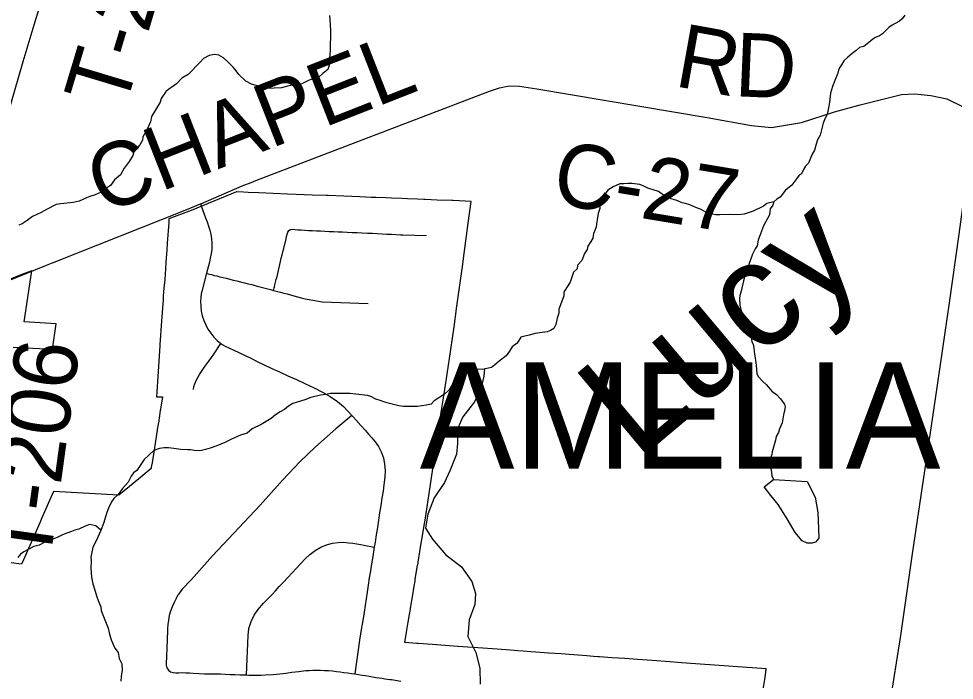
# Model space of a CAD drawing. Extents: x 0 to 34, y 0 to 22.
# Drawn here: x 8.3551 to 8.7724, y 14.1693 to 14.4643 of the extents above; entities that cross this region are included whole.
import ezdxf

# ---------------------------------------------------------------- set-up
doc = ezdxf.new("R2010")
doc.units = 0
for name, color, linetype in [('GM_X_City_Street', 7, 'Continuous'), ('GM_X_Corporation_Text', 7, 'Continuous'), ('GM_X_County_Road', 7, 'Continuous'), ('GM_X_County_Road_Text', 7, 'Continuous'), ('GM_X_Minor_Lake', 7, 'Continuous'), ('GM_X_Minor_River', 7, 'Continuous'), ('GM_X_Minor_River_Text', 7, 'Continuous'), ('GM_X_State_Route', 7, 'Continuous'), ('GM_X_Township_Road', 7, 'Continuous'), ('GM_X_Township_Road_Text', 7, 'Continuous')]:
    doc.layers.add(name, color=color, linetype=linetype)

msp = doc.modelspace()

# ---------------------------------------------------------------- linework, layer by layer
at = {"layer": 'GM_X_City_Street'}
for points in [[(8.6871, 14.16431), (8.68786, 14.16966), (8.68851, 14.17416), (8.68853, 14.17436), (8.67378, 14.17544), (8.65075, 14.17712), (8.6455, 14.1775), (8.63768, 14.17807), (8.63113, 14.17855), (8.62546, 14.17897), (8.61979, 14.17938), (8.61413, 14.17979), (8.61363, 14.17983), (8.61149, 14.17999), (8.60846, 14.18021), (8.60279, 14.18062), (8.60061, 14.18078), (8.59713, 14.18104), (8.59447, 14.18124), (8.59146, 14.18146), (8.58579, 14.18188), (8.58359, 14.18204), (8.58013, 14.1823), (8.57768, 14.18248), (8.57446, 14.18271), (8.56848, 14.18316), (8.56215, 14.18362), (8.55105, 14.18443), (8.54537, 14.18485), (8.5395, 14.18528), (8.53344, 14.18572), (8.53273, 14.18577), (8.52737, 14.18616), (8.52827, 14.19166), (8.52887, 14.19529), (8.52943, 14.19867), (8.52982, 14.20105), (8.52992, 14.20162), (8.52998, 14.20201), (8.53018, 14.20324), (8.53019, 14.20326), (8.53059, 14.20567), (8.53167, 14.21224), (8.53167, 14.21225), (8.53174, 14.21268), (8.5319, 14.21367), (8.53192, 14.21376), (8.53201, 14.21429), (8.53201, 14.21432), (8.5329, 14.21969), (8.53323, 14.22173), (8.53323, 14.22173), (8.53324, 14.22173), (8.53327, 14.22193), (8.53405, 14.22669), (8.53405, 14.2267), (8.53454, 14.22962), (8.53521, 14.2337), (8.53597, 14.23832), (8.53597, 14.23833), (8.53637, 14.24071), (8.53859, 14.25558), (8.54039, 14.26764), (8.54089, 14.27099), (8.54299, 14.28503), (8.54515, 14.29894), (8.54621, 14.30579), (8.54792, 14.31682), (8.54932, 14.32693), (8.55059, 14.33609), (8.55275, 14.35175), (8.55303, 14.35385), (8.55382, 14.35961), (8.55567, 14.3731), (8.557, 14.38285), (8.54884, 14.38318), (8.5483, 14.3832), (8.54176, 14.38346), (8.53637, 14.38367), (8.53585, 14.38369), (8.53299, 14.38381), (8.52856, 14.38399), (8.52608, 14.38408), (8.52146, 14.38427), (8.51901, 14.38437), (8.51437, 14.38455), (8.51235, 14.38463), (8.50727, 14.38484), (8.50017, 14.38512), (8.49308, 14.3854), (8.49244, 14.38543), (8.48598, 14.38569), (8.48597, 14.38569), (8.47888, 14.38597), (8.47505, 14.38612), (8.46221, 14.38663), (8.45751, 14.38685), (8.45534, 14.38694), (8.4524, 14.38706), (8.45227, 14.38706), (8.43204, 14.37875), (8.42214, 14.3751), (8.42203, 14.37337), (8.42141, 14.36427), (8.4212, 14.36125), (8.42081, 14.35554), (8.42045, 14.35017), (8.42027, 14.3482), (8.42025, 14.34788), (8.41992, 14.34408), (8.41962, 14.34069), (8.41962, 14.34069), (8.41951, 14.33899), (8.41887, 14.32955), (8.41814, 14.31883), (8.41811, 14.31844), (8.41733, 14.30693), (8.41657, 14.29575), (8.41926, 14.29568), (8.41925, 14.29562), (8.41854, 14.2912), (8.41836, 14.29002), (8.41828, 14.28955), (8.41794, 14.28741), (8.41787, 14.28691), (8.4178, 14.28649), (8.41757, 14.28507), (8.41755, 14.28492), (8.41732, 14.28348), (8.41694, 14.28111), (8.41692, 14.28095), (8.41691, 14.28086), (8.41565, 14.27298), (8.41459, 14.26627), (8.41446, 14.26546), (8.41442, 14.26522), (8.41425, 14.26415), (8.41425, 14.2641), (8.41418, 14.26369), (8.40864, 14.25916), (8.40448, 14.25575), (8.39972, 14.25186), (8.3707, 14.25346), (8.3655, 14.24169), (8.36452, 14.23947), (8.35728, 14.22306), (8.35642, 14.22112), (8.31928, 14.22581)], [(8.35258, 14.31787), (8.37017, 14.31688), (8.37183, 14.32829), (8.35759, 14.32908), (8.36092, 14.35195), (8.35773, 14.35068), (8.35649, 14.35018), (8.34984, 14.34754)]]:
    msp.add_lwpolyline(points, dxfattribs=at)
at = {"layer": 'GM_X_County_Road'}
msp.add_lwpolyline([(8.33552, 14.34148), (8.36753, 14.35434), (8.36982, 14.35526), (8.37092, 14.35571), (8.42938, 14.37892), (8.43623, 14.38173), (8.43641, 14.3818), (8.45481, 14.38982), (8.45875, 14.39129), (8.46094, 14.39211), (8.56512, 14.43194), (8.56952, 14.43353), (8.5739, 14.43436), (8.57844, 14.43425), (8.58618, 14.43309), (8.66213, 14.42022), (8.68193, 14.41665), (8.69085, 14.41576), (8.7042, 14.41804), (8.71903, 14.42272), (8.73045, 14.42593), (8.74887, 14.43053), (8.75475, 14.43076), (8.76193, 14.43), (8.76915, 14.4286), (8.77664, 14.42485)], dxfattribs=at)
at = {"layer": 'GM_X_Minor_Lake'}
msp.add_line((8.68761, 14.25555), (8.69175, 14.25887), dxfattribs=at)
msp.add_lwpolyline([(8.69175, 14.25887), (8.70685, 14.25788), (8.71035, 14.25098), (8.71156, 14.24411), (8.71182, 14.23689), (8.71194, 14.2327), (8.71057, 14.23083), (8.70905, 14.23047), (8.70677, 14.23051), (8.7045, 14.2315), (8.70152, 14.23516), (8.69782, 14.24131), (8.69394, 14.24765), (8.69059, 14.2517), (8.68761, 14.25555)], dxfattribs=at)
at = {"layer": 'GM_X_Minor_River'}
for points in [[(8.49374, 14.46566), (8.49406, 14.46185), (8.4942, 14.4588), (8.49405, 14.45025), (8.49383, 14.44816), (8.49359, 14.44531), (8.49356, 14.4436), (8.49296, 14.44171), (8.49084, 14.43984), (8.48929, 14.43854), (8.4847, 14.43691), (8.48145, 14.43525), (8.47916, 14.43491), (8.47554, 14.43441), (8.47229, 14.43351), (8.46582, 14.43325), (8.46109, 14.43447), (8.45901, 14.43508), (8.45637, 14.43646), (8.45338, 14.43936), (8.45208, 14.4411), (8.45077, 14.44264), (8.44853, 14.44496), (8.44648, 14.4469), (8.4444, 14.44808), (8.44251, 14.4483), (8.44003, 14.44796), (8.43753, 14.44649), (8.43599, 14.44499), (8.43076, 14.43938), (8.42788, 14.43772), (8.42556, 14.43529), (8.42094, 14.43194), (8.41861, 14.42875), (8.4182, 14.42705), (8.41644, 14.42404), (8.41429, 14.42065), (8.41387, 14.41838), (8.41248, 14.41498), (8.41052, 14.41159), (8.41031, 14.41007), (8.40913, 14.408), (8.40642, 14.405), (8.40601, 14.4033), (8.40445, 14.40066), (8.40212, 14.39766), (8.40054, 14.39465)], [(8.75036, 14.4659), (8.74919, 14.4642), (8.74804, 14.46327), (8.74612, 14.46217), (8.74477, 14.46143), (8.74324, 14.46032), (8.74034, 14.45751), (8.73899, 14.45659), (8.73727, 14.45586), (8.73611, 14.45512), (8.73438, 14.45363), (8.73207, 14.45195), (8.73016, 14.45142), (8.72862, 14.45011), (8.72688, 14.44881), (8.72496, 14.44713), (8.72322, 14.44545), (8.72205, 14.44376), (8.72088, 14.44188), (8.72046, 14.43999), (8.71908, 14.43678), (8.71808, 14.43413), (8.71727, 14.43111), (8.71682, 14.42712), (8.71641, 14.42523), (8.71578, 14.42162), (8.7148, 14.41993), (8.714, 14.41766), (8.71258, 14.41236), (8.71141, 14.41029), (8.71081, 14.4084), (8.71, 14.40575), (8.70902, 14.40387), (8.70803, 14.40141), (8.70743, 14.3999), (8.70608, 14.39859), (8.70511, 14.39709), (8.70431, 14.3952), (8.70316, 14.39446)], [(8.40054, 14.39465), (8.39785, 14.39241), (8.39609, 14.38997), (8.39379, 14.38849), (8.39186, 14.387), (8.38918, 14.38572), (8.38689, 14.385), (8.38536, 14.38445), (8.3821, 14.38299), (8.37943, 14.38228), (8.37391, 14.3818), (8.37181, 14.38146), (8.36759, 14.37925), (8.3651, 14.37796), (8.36127, 14.37613), (8.35895, 14.37427), (8.35665, 14.37279), (8.35512, 14.37224)], [(8.70316, 14.39446), (8.70199, 14.39296), (8.69985, 14.38995), (8.69716, 14.38791), (8.69482, 14.38472), (8.69329, 14.38379), (8.69194, 14.38268), (8.69153, 14.38116), (8.69036, 14.37947), (8.68994, 14.37682), (8.68738, 14.37192), (8.68599, 14.36833), (8.68499, 14.36549), (8.68457, 14.36303), (8.6836, 14.36171), (8.68242, 14.35926), (8.68082, 14.35473), (8.68042, 14.35321), (8.67981, 14.35113), (8.67902, 14.34962), (8.67842, 14.34735), (8.67739, 14.34281), (8.67679, 14.34091), (8.67657, 14.3394), (8.67671, 14.33654), (8.67725, 14.33463), (8.67797, 14.33196), (8.67885, 14.32814), (8.67978, 14.32679), (8.68033, 14.32564), (8.68069, 14.32411), (8.68179, 14.32219), (8.68214, 14.32028), (8.68269, 14.31913), (8.68305, 14.3176), (8.68321, 14.31608), (8.68338, 14.31474), (8.68354, 14.31303), (8.68371, 14.31189), (8.68406, 14.30979), (8.68437, 14.30598), (8.68511, 14.30463), (8.68698, 14.30251), (8.68847, 14.30115), (8.69109, 14.29825), (8.69315, 14.2967), (8.69483, 14.29495), (8.69669, 14.29245), (8.69705, 14.2913), (8.69664, 14.2896), (8.69623, 14.2877), (8.6956, 14.2841), (8.69441, 14.28146), (8.69401, 14.27975), (8.69303, 14.27806), (8.69262, 14.27636), (8.6912, 14.27125), (8.69099, 14.26992), (8.69059, 14.26878), (8.69056, 14.26707), (8.69016, 14.26575), (8.69033, 14.26441), (8.69068, 14.26308), (8.69102, 14.26041), (8.69175, 14.25887)], [(8.69192, 14.38261), (8.68888, 14.38197), (8.68734, 14.38067), (8.68274, 14.37847), (8.67873, 14.3772), (8.67587, 14.37687), (8.67264, 14.37693), (8.66789, 14.37682), (8.66599, 14.37686), (8.66334, 14.37748), (8.66164, 14.37808), (8.65956, 14.37925), (8.65711, 14.38006), (8.65447, 14.38124), (8.65257, 14.38185), (8.65106, 14.38225), (8.64861, 14.38325), (8.64615, 14.38405), (8.64275, 14.38563), (8.6405, 14.3872), (8.63577, 14.3888), (8.63389, 14.38959), (8.63219, 14.39038), (8.62858, 14.39083), (8.62687, 14.39086), (8.62497, 14.3907), (8.62326, 14.39073), (8.6202, 14.38926), (8.61789, 14.38778), (8.61594, 14.38515), (8.61436, 14.38138), (8.61433, 14.37967), (8.61353, 14.3774), (8.6131, 14.37456), (8.61289, 14.37285), (8.61267, 14.37133), (8.61148, 14.3685), (8.61126, 14.36641), (8.61028, 14.36491), (8.60891, 14.36284), (8.6087, 14.36132), (8.60753, 14.35963), (8.60634, 14.35642), (8.6044, 14.35436), (8.60418, 14.35284), (8.60264, 14.35135), (8.60204, 14.34946), (8.60104, 14.34681), (8.59948, 14.34437), (8.5983, 14.3423), (8.59828, 14.34077), (8.59728, 14.33794), (8.59609, 14.33473), (8.59606, 14.33302), (8.59526, 14.33075), (8.59464, 14.32791), (8.59385, 14.32621), (8.59232, 14.32528), (8.59079, 14.32474), (8.58755, 14.32423), (8.58545, 14.32388), (8.58278, 14.32317), (8.58087, 14.32282), (8.57915, 14.32228), (8.57739, 14.31965), (8.57527, 14.31798), (8.5741, 14.31609), (8.57255, 14.31403), (8.56947, 14.31161), (8.56754, 14.30993), (8.566, 14.30882), (8.5639, 14.30829), (8.5618, 14.30794), (8.5599, 14.30798), (8.55742, 14.30764), (8.5559, 14.30729), (8.55437, 14.30674), (8.55187, 14.30527), (8.54857, 14.30114), (8.54701, 14.29869), (8.54507, 14.29683), (8.54046, 14.29386), (8.53911, 14.29237), (8.53682, 14.29203), (8.53301, 14.29133), (8.52674, 14.29144), (8.52465, 14.29167), (8.52295, 14.29208), (8.52048, 14.29269), (8.5184, 14.2933), (8.51633, 14.2941), (8.51443, 14.2947), (8.51217, 14.29588), (8.51066, 14.29629), (8.50554, 14.29695), (8.50288, 14.29719), (8.50003, 14.29724), (8.49414, 14.29715), (8.49204, 14.29681), (8.48975, 14.29647), (8.48536, 14.2954)], [(8.56286, 14.30812), (8.5626, 14.30486), (8.56137, 14.29975), (8.55842, 14.29353), (8.55317, 14.28678), (8.55099, 14.28168), (8.55087, 14.27484), (8.55041, 14.2701), (8.54743, 14.26274), (8.54506, 14.25746), (8.54038, 14.2507), (8.5376, 14.24333), (8.53654, 14.23708), (8.53969, 14.23227), (8.54547, 14.22533), (8.5526, 14.21988), (8.55724, 14.21334), (8.55886, 14.20799), (8.55858, 14.20305), (8.556, 14.19625), (8.55549, 14.18885), (8.55898, 14.18176), (8.56076, 14.17469), (8.56102, 14.16766)], [(8.48536, 14.2954), (8.48268, 14.29431), (8.47734, 14.29269), (8.47542, 14.29158), (8.47368, 14.29009), (8.47176, 14.28899), (8.46965, 14.28769), (8.46772, 14.28601), (8.4633, 14.28343), (8.45928, 14.28141), (8.45696, 14.27955), (8.4541, 14.27865), (8.45007, 14.27681), (8.44701, 14.27535), (8.44356, 14.27389), (8.4405, 14.2728), (8.4384, 14.27226), (8.43668, 14.27172), (8.43516, 14.27156), (8.43345, 14.27178), (8.43194, 14.272), (8.43041, 14.27202), (8.42738, 14.27227), (8.42434, 14.2727), (8.42188, 14.27294), (8.41998, 14.27297), (8.41788, 14.27263), (8.41539, 14.27172), (8.41114, 14.2678), (8.40783, 14.26291), (8.40629, 14.2618), (8.40532, 14.26029), (8.40394, 14.25765), (8.40142, 14.25485), (8.39948, 14.25222), (8.39755, 14.25035), (8.39657, 14.24884), (8.39519, 14.24602), (8.3944, 14.24413), (8.39299, 14.23921), (8.3916, 14.23581), (8.38982, 14.23185), (8.38825, 14.22864), (8.38722, 14.22428), (8.38738, 14.22257), (8.38733, 14.21934), (8.38764, 14.21534), (8.38816, 14.21229), (8.38925, 14.20903), (8.38978, 14.20693), (8.3905, 14.20483), (8.39179, 14.20214), (8.39195, 14.20043), (8.39268, 14.19851), (8.39505, 14.19257), (8.3954, 14.19048), (8.3963, 14.18742), (8.39794, 14.18359), (8.39943, 14.18166), (8.39995, 14.17899), (8.40106, 14.17668), (8.4012, 14.17383), (8.40077, 14.17098), (8.40074, 14.16889)], [(8.39175, 14.23618), (8.38955, 14.23813), (8.3867, 14.23875), (8.38479, 14.23802), (8.38192, 14.23674), (8.3802, 14.2362), (8.37867, 14.23566), (8.37657, 14.23493), (8.37465, 14.2342), (8.37235, 14.23291), (8.36642, 14.23074), (8.36431, 14.22963), (8.36183, 14.22891), (8.35742, 14.22652), (8.35588, 14.22559), (8.35471, 14.22409)]]:
    msp.add_lwpolyline(points, dxfattribs=at)
at = {"layer": 'GM_X_State_Route'}
msp.add_lwpolyline([(8.73524, 14.1), (8.73859, 14.12228), (8.74369, 14.15835), (8.74865, 14.18932), (8.75382, 14.22564), (8.75935, 14.26268), (8.76408, 14.29478), (8.77026, 14.33757), (8.77463, 14.36821), (8.77791, 14.39245), (8.77871, 14.39788)], dxfattribs=at)
at = {"layer": 'GM_X_Township_Road'}
for points in [[(8.33639, 14.34667), (8.33884, 14.36494), (8.34137, 14.37939), (8.34327, 14.38794), (8.34493, 14.39958), (8.34707, 14.4105), (8.35158, 14.42618), (8.35704, 14.44518), (8.36206, 14.4616), (8.3761, 14.50793), (8.40375, 14.59925)], [(8.43623, 14.38173), (8.43723, 14.37875), (8.43848, 14.37552), (8.43914, 14.37368), (8.43992, 14.37138), (8.44032, 14.37007), (8.44065, 14.36882), (8.4409, 14.36739), (8.44114, 14.36596), (8.44125, 14.36452), (8.44128, 14.36309), (8.44124, 14.36169), (8.44111, 14.3603), (8.44088, 14.35893), (8.44057, 14.35747), (8.44022, 14.35581), (8.4398, 14.3541), (8.43936, 14.35241), (8.43893, 14.35078), (8.43693, 14.34327), (8.43657, 14.34161), (8.43635, 14.33992), (8.43624, 14.33822), (8.4363, 14.33606), (8.43655, 14.33391), (8.43701, 14.3318), (8.43767, 14.32973), (8.43852, 14.32774), (8.43955, 14.32584), (8.44076, 14.32405), (8.44213, 14.32237), (8.44365, 14.32084), (8.44532, 14.31945), (8.44591, 14.31905), (8.44728, 14.31826), (8.45105, 14.31649), (8.45336, 14.31546), (8.4586, 14.31294), (8.4615, 14.3115), (8.46463, 14.30997), (8.46796, 14.3084), (8.47149, 14.30679), (8.47519, 14.30512), (8.47905, 14.30337), (8.48301, 14.30153), (8.48691, 14.2997), (8.49064, 14.29783), (8.4941, 14.29583), (8.49726, 14.29367), (8.49999, 14.29133), (8.50367, 14.28745), (8.50621, 14.28469), (8.5063, 14.28459), (8.50806, 14.2826), (8.50966, 14.28078), (8.51114, 14.2791), (8.51263, 14.2774), (8.51414, 14.27557), (8.51555, 14.2735), (8.51682, 14.27116), (8.5178, 14.26852), (8.51835, 14.26568), (8.51856, 14.26281), (8.51848, 14.25992), (8.51798, 14.2565), (8.51766, 14.2537), (8.51716, 14.25048), (8.51663, 14.24721), (8.51612, 14.24392), (8.51561, 14.24065), (8.5151, 14.2374), (8.51457, 14.23416), (8.51406, 14.23092), (8.51373, 14.2287), (8.51304, 14.22449), (8.51253, 14.22129), (8.51202, 14.21811), (8.5115, 14.21493), (8.51098, 14.21178), (8.5105, 14.20868), (8.51005, 14.20561), (8.50959, 14.2026), (8.50914, 14.1997), (8.5087, 14.19688), (8.50829, 14.19427), (8.50793, 14.19197), (8.50762, 14.19006), (8.5072, 14.18722), (8.50512, 14.17214)], [(8.4688, 14.34313), (8.46904, 14.34426), (8.46919, 14.34481), (8.46941, 14.34569), (8.4697, 14.34684), (8.46999, 14.34806), (8.47033, 14.34935), (8.47066, 14.35068), (8.47098, 14.35203), (8.4713, 14.35338), (8.47161, 14.35474), (8.47193, 14.35611), (8.47226, 14.35751), (8.4726, 14.35894), (8.47295, 14.36039), (8.47331, 14.36185), (8.47368, 14.3633), (8.47405, 14.36476), (8.47438, 14.36611), (8.47464, 14.36723), (8.47487, 14.36823), (8.47513, 14.36917), (8.47562, 14.36993), (8.47633, 14.37032), (8.47713, 14.37039), (8.47824, 14.37031), (8.47963, 14.3702), (8.48116, 14.37011), (8.48276, 14.37001), (8.48442, 14.36992), (8.48614, 14.36985), (8.48792, 14.36977), (8.48978, 14.36969), (8.4917, 14.36959), (8.49364, 14.36949), (8.49558, 14.36938), (8.49756, 14.36929), (8.49958, 14.3692), (8.50169, 14.36911), (8.50387, 14.36903), (8.5061, 14.36893), (8.50837, 14.36884), (8.51063, 14.36874), (8.51286, 14.36863), (8.51503, 14.36851), (8.51717, 14.3684), (8.51927, 14.3683), (8.52133, 14.36819), (8.52336, 14.36809), (8.52539, 14.368), (8.52652, 14.36795), (8.537, 14.36768)], [(8.43893, 14.35078), (8.43959, 14.35057), (8.44017, 14.35042), (8.44108, 14.35018), (8.44229, 14.34987), (8.44354, 14.34962), (8.44489, 14.34923), (8.44628, 14.34889), (8.44773, 14.34854), (8.44924, 14.34819), (8.45081, 14.34773), (8.45241, 14.34744), (8.45408, 14.347), (8.45577, 14.34654), (8.45746, 14.3461), (8.45909, 14.34573), (8.46154, 14.34504), (8.46748, 14.34349), (8.4688, 14.34313), (8.47193, 14.3423), (8.47334, 14.34193), (8.47484, 14.34155), (8.47637, 14.34115), (8.47787, 14.34075), (8.47944, 14.34033), (8.4811, 14.33988), (8.48287, 14.33942), (8.48382, 14.33919), (8.49044, 14.33807), (8.51096, 14.33734)], [(8.43306, 14.29891), (8.43329, 14.30024), (8.43369, 14.3015), (8.43433, 14.30293), (8.43506, 14.30435), (8.43583, 14.30571), (8.43662, 14.30694), (8.43753, 14.30832), (8.43865, 14.30985), (8.43989, 14.31153), (8.44109, 14.31317), (8.44219, 14.31469), (8.44532, 14.31945)], [(8.50367, 14.28745), (8.4965, 14.28148), (8.48745, 14.27334), (8.48047, 14.26669), (8.4729, 14.25863), (8.46279, 14.24745), (8.44159, 14.22476), (8.43213, 14.21424), (8.42802, 14.20988), (8.42679, 14.20824), (8.42628, 14.20744), (8.426, 14.20705), (8.42565, 14.20646), (8.4253, 14.20577), (8.42491, 14.20489), (8.4244, 14.20396), (8.42354, 14.20205), (8.42283, 14.20011), (8.42226, 14.19815), (8.42188, 14.19619), (8.42165, 14.19426), (8.42153, 14.19236), (8.42147, 14.19047), (8.42138, 14.18859), (8.4213, 14.18667), (8.42122, 14.18471), (8.42117, 14.18279), (8.42111, 14.18094), (8.421, 14.17915), (8.42091, 14.17757), (8.42093, 14.17613), (8.42124, 14.17489), (8.42187, 14.17384), (8.42282, 14.17312), (8.42393, 14.17278), (8.42516, 14.17271), (8.42654, 14.17267), (8.42804, 14.17272), (8.42964, 14.1727), (8.43132, 14.17263), (8.43301, 14.17246), (8.43792, 14.17218), (8.43956, 14.17221), (8.44131, 14.17222), (8.44317, 14.17218), (8.44515, 14.17212), (8.44726, 14.17204), (8.44942, 14.17197), (8.45157, 14.1719), (8.45368, 14.17182), (8.45572, 14.17174), (8.45669, 14.1717), (8.45771, 14.17166), (8.45964, 14.1716), (8.46153, 14.17158), (8.46333, 14.17161), (8.46501, 14.17174), (8.46869, 14.17186), (8.47157, 14.17218), (8.47431, 14.17252), (8.47694, 14.1729), (8.48009, 14.17328), (8.48313, 14.17367), (8.4847, 14.17371), (8.48631, 14.17376), (8.48799, 14.1738), (8.48971, 14.17379), (8.49145, 14.17374), (8.49325, 14.17363), (8.49503, 14.17348), (8.4968, 14.17328), (8.49852, 14.17307), (8.50018, 14.17284), (8.50185, 14.17262), (8.5035, 14.17238), (8.50483, 14.17218), (8.50511, 14.17214), (8.50512, 14.17214), (8.5067, 14.1719), (8.50829, 14.17165), (8.50986, 14.17139), (8.51141, 14.17112), (8.51292, 14.17088), (8.5144, 14.17063), (8.51584, 14.1704), (8.5172, 14.1702), (8.51846, 14.17003), (8.51961, 14.16987), (8.5206, 14.16973), (8.52136, 14.16962), (8.52563, 14.16897)], [(8.45669, 14.1717), (8.45745, 14.18928), (8.45783, 14.19245), (8.45884, 14.1956), (8.46018, 14.19828), (8.46185, 14.20076), (8.46433, 14.20364), (8.46798, 14.20737), (8.4696, 14.20924), (8.47136, 14.21116), (8.47322, 14.21312), (8.47512, 14.21513), (8.47706, 14.21719), (8.479, 14.21928), (8.48094, 14.22138), (8.48291, 14.22344), (8.48504, 14.22539), (8.48736, 14.22715), (8.48986, 14.22864), (8.49246, 14.22976), (8.4951, 14.23048), (8.49764, 14.23081), (8.50002, 14.23084), (8.50219, 14.23067), (8.50417, 14.23042), (8.50597, 14.23011), (8.50767, 14.2298), (8.50911, 14.22951), (8.51373, 14.2287)]]:
    msp.add_lwpolyline(points, dxfattribs=at)

# ---------------------------------------------------------------- texts
at = {"layer": 'GM_X_Corporation_Text'}
msp.add_text('AMELIA', height=0.047348, rotation=0, dxfattribs=at).set_placement((8.53402, 14.26371))
at = {"layer": 'GM_X_County_Road_Text'}
for s, height, rotation, p in [('R', 0.02841, 349.8344, (8.64701, 14.43433)), ('D', 0.02841, 357.573, (8.67407, 14.42976)), ('CHAPEL', 0.028409, 21.4425, (8.39283, 14.377)), ('C-27', 0.028409, 350.5421, (8.59224, 14.38217))]:
    msp.add_text(s, height=height, rotation=rotation, dxfattribs=at).set_placement(p)
at = {"layer": 'GM_X_Minor_River_Text'}
msp.add_text('Lucy', height=0.047349, rotation=40.0034, dxfattribs=at).set_placement((8.63088, 14.26681))
at = {"layer": 'GM_X_Township_Road_Text'}
for rotation, p in [(73.2221, (8.40226, 14.42291)), (82.1482, (8.36889, 14.22046))]:
    msp.add_text('T-206', height=0.028409, rotation=rotation, dxfattribs=at).set_placement(p)

doc.saveas('drawing.dxf')
